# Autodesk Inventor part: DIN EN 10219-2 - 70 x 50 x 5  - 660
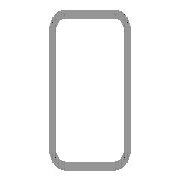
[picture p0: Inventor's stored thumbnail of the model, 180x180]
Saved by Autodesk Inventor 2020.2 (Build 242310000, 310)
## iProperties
_CCFamilyMember: 17
_CCFamilyDisplayName: DIN EN 10219-2 (Rechteckiges Hohlprofil - Kaltgeformt) - Kaltgeformte, geschweißte Baustahl-Hohlprofile aus unlegiertem Feinkorn-Baustahl
_FrameMemberDoc: Frame Member File
_Version: 15.0.0
_GetPNFromCC: 1
IsCustomPart: 1
Created: 2019-01
Part Number: DIN EN 10219-2 - 70 x 50 x 5  - 660
Material: Stahl, weich
Description: Kaltgeformte, geschweißte Baustahl-Hohlprofile aus unlegiertem Feinkorn-Baustahl
Document SubType Name: Modeling
Standard: DIN
Designer: lutzd
Standard Revision: 2006-07
Standards Organization: DIN
Language: de-DE
Size Designation: 70 x 50 x 5
Categories: <MemberInstance><Categories><Category DisplayName="Profile" InternalName="089c4875-fa83-4c05-b084-43b9cc11f5ed" Mnemonic="GRDR"><CategoryParameter DisplayName="
Stock Number: 70 x 50 x 5
Mass: 5318.63 g
Surface Area: 2750.89 cm^2
Volume: 677.533 cm^3
Density: 7.85 g/cm^3
Appearance: Semi-Polished(8)
G_L: 660,000 mm
G_W: 50,000 mm
G_H: 70,000 mm
+CB3ABCA7-6EF8-40A0-9BC2-D50BA99696A8+SCHNITTDETAIL1: Schnittwinkel 90,00 grd
DocNumber: ADSK-014452
Folder: .
Mass: 5,319 kg
VLT_Material: Stahl, weich
Dimensions: 50x70x660 mm
Title: Profil-Bauteil
Author: lutzd
Revision Number: -
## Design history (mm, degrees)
node "Startebene"
node "Endebene"
sketch "Skizze"
  geometry: L1 (-25, -25)-(-25, 25); L2 (-15, 35)-(15, 35); L3 (25, 25)-(25, -25); L4 (15, -35)-(-15, -35); L5 (-15, 30)-(15, 30); L6 (20, 25)-(20, -25); L7 (15, -30)-(-15, -30); L8 (-20, -25)-(-20, 25); L9 (0, 51.899)-(0, -51.899) reference; L10 (-37.899, 0)-(37.899, 0) reference; A1 r 10 centre (-15, -25) between (-25, -25) and (-15, -35); A2 r 10 centre (-15, 25) between (-15, 35) and (-25, 25); A3 r 10 centre (15, 25) between (25, 25) and (15, 35); A4 r 10 centre (15, -25) between (15, -35) and (25, -25); A5 r 5 centre (-15, 25) between (-15, 30) and (-20, 25); A6 r 5 centre (15, 25) between (20, 25) and (15, 30); A7 r 5 centre (15, -25) between (15, -30) and (20, -25); A8 r 5 centre (-15, -25) between (-20, -25) and (-15, -30)
  constraints: 16 end point, 16 point on circle, 8 centre point, 8 tangent, 4 parallel, 3 equal radius, 2 perpendicular, 7 other
  dimensions: "d7" = 10 radius of A1 (= G_IR); "d10" = 70 distance between parallel lines of L2 L4 (= G_H); "d11" = 50 distance between parallel lines of L1 L3 (= G_W); "d12" = 5 distance between parallel lines of L3 L6 (= G_T); "d15" = 35 distance between parallel lines of L2 L10 (= 0.5 x d10); "d16" = 25 distance between parallel lines of L9 L3 (= 0.5 x d11)
extrude "Körper" new body sketch "Skizze" stored distance "d3" = 660 (= G_L); taper "d4" = 0 deg
node "Driven Length"
  sketch "Sketch3"
    geometry: L1 (0, 0)-(10, 0) reference
    constraints: 2 end point, 1 horizontal
  workplane "Work Plane3"
  sketch "Sketch4"
    geometry: L1 (-2, 0)-(12, 0) reference; L2 (-2, 660)-(12, 660) reference
    dimensions: "d18" = 660 distance between parallel lines of L1 L2 (derived)
workplane "Arbeitsebene4"
feature "Trennen1"
sketch "Skizze5"
  geometry: L1 (660, -50)-(660, 0) reference; L2 (660, -25)-(544, -25); L3 (98, -9)-(98, -41); L4 (440, -9)-(440, -41); 11 further points
  constraints: 6 end point, 5 coincident, 5 midpoint, 2 horizontal alignment, 2 vertical, 1 horizontal, 1 point on line
  dimensions: "d19" = 90 distance of point (544, -25) point (634, -25); "d20" = 116 distance of L2.start L2.end; "d21" = 32 distance of L3.start L3.end; "d22" = 32 distance of L4.start L4.end (= d21); "d24" = 220 distance between parallel lines of L1 L4; "d25" = 342 distance between parallel lines of L4 L3
hole "Bohrung1" sketch "Skizze5" at (544, -25), (634, -25), (440, -41), (440, -9), (98, -41), (98, -9) diameter "d26" = 6.647; stored, may be unused: countersink angle "d30" = 90 deg, drill point angle "d32" = 118 deg; dims "d27" = 16, "d28" = 4, "d29" = 2, "d31" = 8
sketch "Skizze6"
  geometry: L1 (-30, 0)-(0, 0) reference; L2 (-15, 0)-(-15, 436); 5 further points
  constraints: 3 point on line, 2 end point, 1 coincident, 1 midpoint, 1 vertical
  dimensions: "d33" = 32 distance of point (-15, 174) point (-15, 206); "d34" = 32 distance of point (-15, 404) point (-15, 436) (= d33); "d35" = 206 distance from line of point (-15, 206) L1; "d36" = 436 distance of L2.start L2.end
hole "Bohrung2" sketch "Skizze6" at (-15, 436), (-15, 404), (-15, 174), (-15, 206) diameter "d37" = 6.647; stored, may be unused: countersink angle "d41" = 90 deg, drill point angle "d43" = 118 deg; dims "d38" = 16, "d39" = 4, "d40" = 2, "d42" = 8
sketch "Skizze7"
  geometry: L1 (0, 50)-(0, 0) reference; L2 (0, 25)-(111, 25); 4 further points
  constraints: 2 end point, 2 point on line, 1 coincident, 1 horizontal, 1 midpoint
  dimensions: "d44" = 111 distance of L2.start L2.end; "d45" = 80 distance of point (111, 25) point (31, 25); "d53" = 40 distance of point (71, 25) point (31, 25) (= 0.5 x d45)
hole "Bohrung3" sketch "Skizze7" diameter "d46" = 6.647; stored, may be unused: countersink angle "d50" = 90 deg, drill point angle "d52" = 118 deg; dims "d47" = 16, "d48" = 4, "d49" = 2, "d51" = 8
hole "Bohrung4" sketch "Skizze7" diameter "d54" = 22; stored, may be unused: countersink angle "d58" = 90 deg, drill point angle "d60" = 118 deg; dims "d55" = 48, "d56" = 4, "d57" = 2, "d59" = 8
body "Solid1"
other parameters: "G_W" = 50 [user parameter; used in 1 equation term], "G_H" = 70 [user parameter; used in 1 equation term], "G_T" = 5 [user parameter; used in 1 equation term], "G_IR" = 10 [user parameter; used in 1 equation term], "G_L" = 660 (= d18) [user parameter; used in 1 equation term], "G_OFFSET_START" = 0 [user parameter; used in 1 equation term], "d13" = 0 (computed from G_OFFSET_START), "d17" = 90 deg
